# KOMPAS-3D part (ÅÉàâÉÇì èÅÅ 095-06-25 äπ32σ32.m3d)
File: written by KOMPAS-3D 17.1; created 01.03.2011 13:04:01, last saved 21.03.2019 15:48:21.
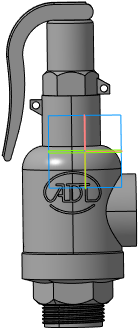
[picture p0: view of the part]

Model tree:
1. Операция без истории:1

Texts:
  Viktor2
